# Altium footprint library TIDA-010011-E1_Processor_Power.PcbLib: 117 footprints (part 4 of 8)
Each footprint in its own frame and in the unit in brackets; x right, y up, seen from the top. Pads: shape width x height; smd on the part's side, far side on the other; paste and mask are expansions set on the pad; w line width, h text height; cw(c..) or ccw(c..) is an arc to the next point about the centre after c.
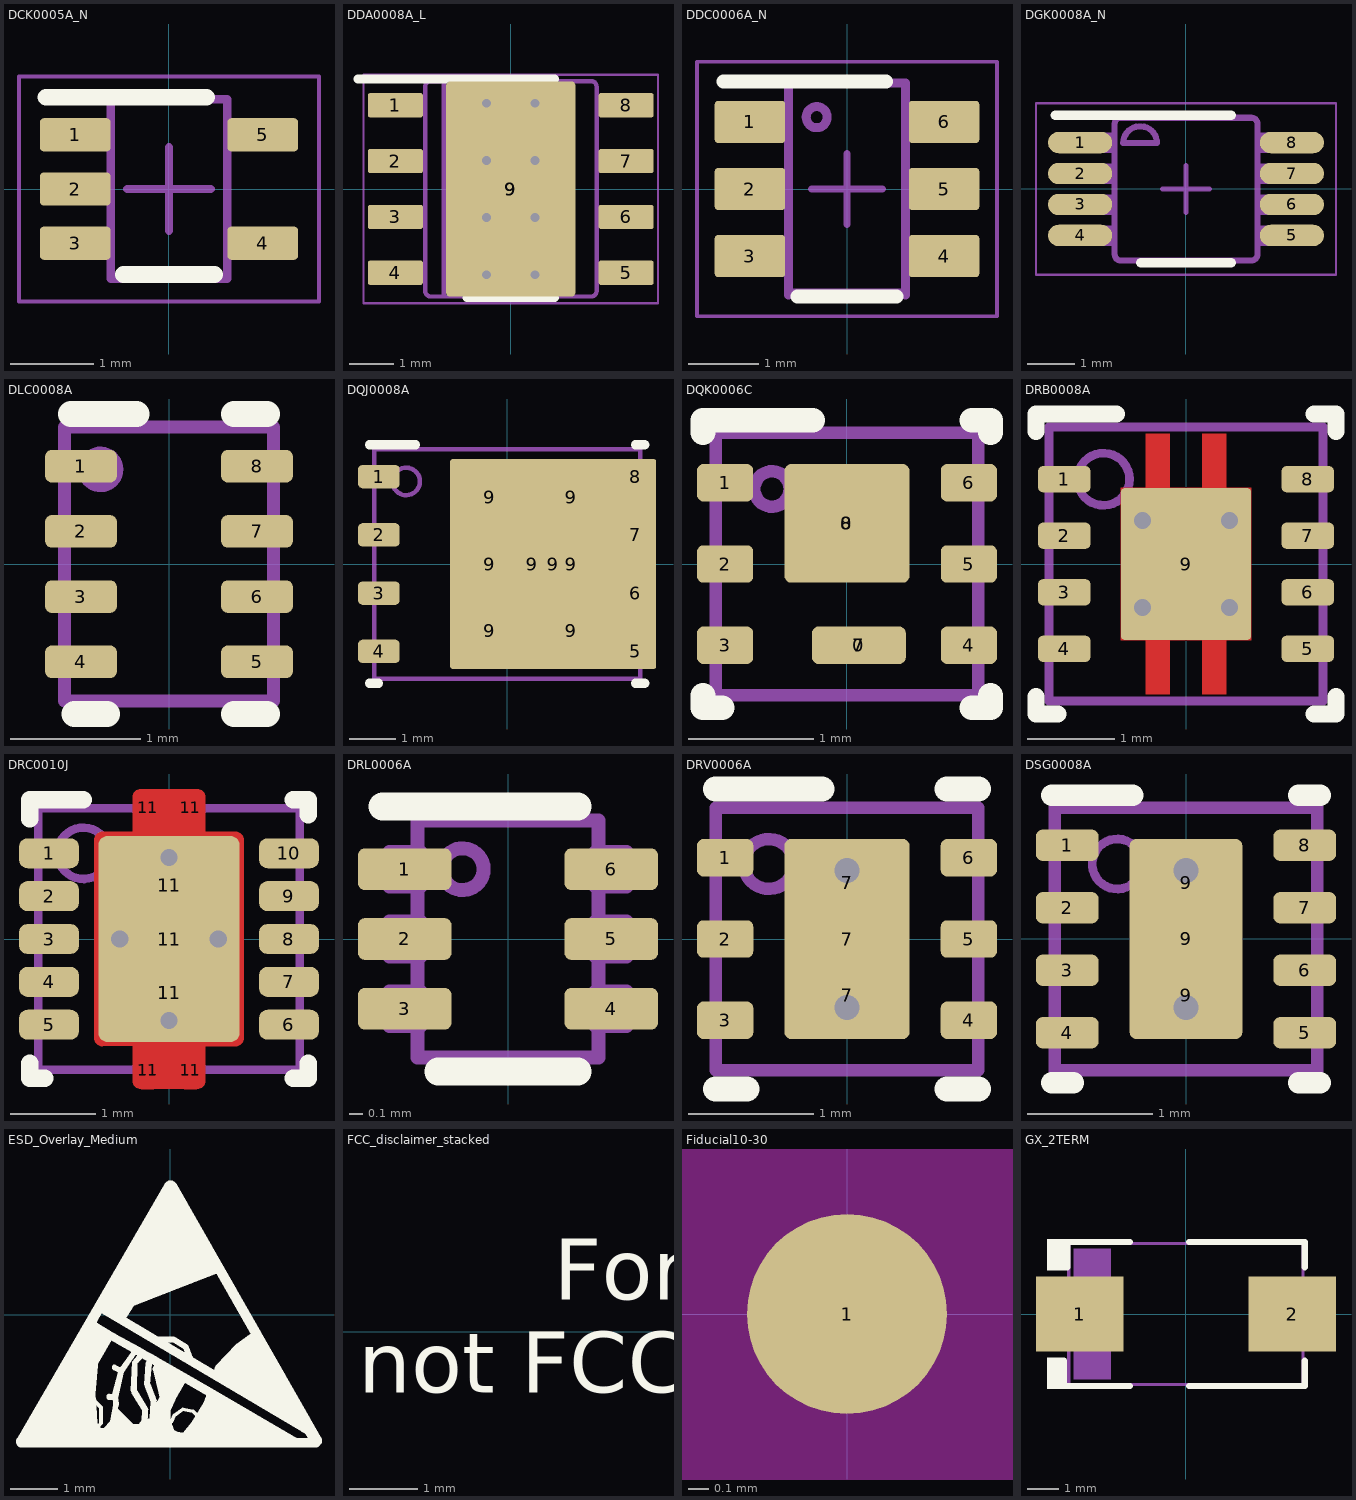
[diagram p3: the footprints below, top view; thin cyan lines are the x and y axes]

## DCK0005A_N [mm] "SOT353, 5-Leads, Body 2x1.3mm, Pitch 0.65mm, Lead Span 2.1mm, IPC Medium Density"
height 1.1
pads (5):
  rrect25% 0.85x0.4 smd: 1(-1.125,0.65) 2(-1.125,0) 3(-1.125,-0.65) 4(1.125,-0.65) 5(1.125,0.65)
Top Overlay:
  lines w0.2: -1.475,1.1 0.45,1.1 ; -0.55,-1.025 0.55,-1.025
Mechanical 5:
  lines w0.1: -0.7,-1.075 0.7,-1.075 0.7,1.075 -0.7,1.075 -0.7,-1.075
  lines w0.127: -0.865,0.762 -0.853,0.762 ; -0.711,-0.763 -0.853,-0.763 -0.865,-0.763 -0.959,-0.763 -1.143,-0.763 -1.143,-0.538 -0.959,-0.538 -0.865,-0.538 -0.853,-0.538 -0.711,-0.538 ; -0.711,-0.113 -0.853,-0.113 -0.865,-0.113 -0.959,-0.113 -1.143,-0.113 -1.143,0.112 -0.959,0.112 -0.865,0.112 -0.853,0.112 -0.711,0.112 ; -0.711,0.537 -0.853,0.537 -0.865,0.537 -0.959,0.537 -1.143,0.537 -1.143,0.762 -0.959,0.762 -0.711,0.762 ; 0.711,-0.763 0.847,-0.763 0.859,-0.763 0.953,-0.763 1.137,-0.763 1.137,-0.538 0.953,-0.538 0.859,-0.538 0.847,-0.538 0.711,-0.538 ; 0.711,0.537 0.847,0.537 0.859,0.537 0.953,0.537 1.137,0.537 1.137,0.762 0.953,0.762 0.859,0.762 0.847,0.762 0.711,0.762
  text ".Designator" at 0.178,-0.718 h0.51
Mechanical 15:
  lines w0.05: -1.8,-1.35 1.8,-1.35 1.8,1.35 -1.8,1.35 -1.8,-1.35
  lines w0.1: -0.5,0 0.5,0 ; 0,-0.5 0,0.5
3D body "DCK0005A.stp": height 0.95, standoff 0, extent -1.14,-1 1.14,1

## DDA0008A_L [mm] "SOIC, 8-Leads, Body 4.95x3.95mm, Pitch 1.27mm, Thermal Pad 2.29.2x2.29mm, IPC High Density"
height 1.68
pads (11):
  rrect18% 1.25x0.55 smd: 1(-2.625,1.905) 2(-2.625,0.635) 3(-2.625,-0.635) 4(-2.625,-1.905) 5(2.625,-1.905) 6(2.625,-0.635) 7(2.625,0.635) 8(2.625,1.905)
  rrect7% 2.95x4.9 smd paste-1.5 mask-1.5: 9(0,0)
  rrect50% 2.34x2.34 on Top Paste: 9(0,0)
  rrect50% 2.34x2.34 on Top Solder: 9(0,0)
via -0.55,0.65 diameter 0.5 hole 0.2
via 0.55,0.65 diameter 0.5 hole 0.2
via -0.55,-0.65 diameter 0.5 hole 0.2
via 0.55,-0.65 diameter 0.5 hole 0.2
via 0.55,1.95 diameter 0.5 hole 0.2
via -0.55,1.95 diameter 0.5 hole 0.2
via -0.55,-1.95 diameter 0.5 hole 0.2
via 0.55,-1.95 diameter 0.5 hole 0.2
Top Overlay:
  lines w0.2: -3.475,2.5 1,2.5 ; -1,-2.475 1,-2.475
Mechanical 5:
  lines w0.1: -1.946,-2.321 ccw(c-1.819,-2.32) -1.82,-2.447 ; -1.946,-2.321 -1.946,-2.32 -1.946,2.329 ; -1.946,2.33 -1.946,2.329 ; -1.524,-2.447 -1.524,2.456 ; -1.946,2.33 cw(c-1.819,2.329) -1.82,2.456 ; -1.819,-2.447 1.826,-2.447 1.827,-2.447 ccw(c1.826,-2.32) 1.953,-2.321 1.953,-2.32 1.953,2.329 ; -1.82,-2.447 -1.819,-2.447 ; -1.82,2.456 -1.819,2.456 ; -1.819,2.456 1.826,2.456 1.827,2.456 cw(c1.826,2.329) 1.953,2.33 ; 1.953,2.329 1.953,2.33 ; -2.975,-2.091 -2.975,-1.71 -2.614,-1.71 -2.497,-1.71 -2.473,-1.71 -2.144,-1.71 -1.946,-1.71 -1.946,-2.091 -2.144,-2.091 -2.473,-2.091 -2.497,-2.091 -2.614,-2.091 -2.975,-2.091 ; -2.975,-0.821 -2.975,-0.44 -2.614,-0.44 -2.497,-0.44 -2.473,-0.44 -2.144,-0.44 -1.946,-0.44 -1.946,-0.821 -2.144,-0.821 -2.473,-0.821 -2.497,-0.821 -2.614,-0.821 -2.975,-0.821 ; -2.975,0.449 -2.975,0.83 -2.614,0.83 -2.497,0.83 -2.473,0.83 -2.144,0.83 -1.946,0.83 -1.946,0.449 -2.144,0.449 -2.473,0.449 -2.497,0.449 -2.614,0.449 -2.975,0.449 ; -2.975,1.719 -2.975,2.1 -2.614,2.1 -2.497,2.1 -2.473,2.1 -2.144,2.1 -1.946,2.1 -1.946,1.719 -2.144,1.719 -2.473,1.719 -2.497,1.719 -2.614,1.719 -2.975,1.719 ; -0.632,1.16 ccw(c-0.632,1.478) -0.632,1.795 ccw(c-0.632,1.478) -0.632,1.16 ; 1.953,-2.091 1.953,-1.71 2.15,-1.71 2.479,-1.71 2.503,-1.71 2.621,-1.71 2.981,-1.71 2.981,-2.091 2.621,-2.091 2.503,-2.091 2.479,-2.091 2.15,-2.091 1.953,-2.091 ; 1.953,-0.821 1.953,-0.44 2.15,-0.44 2.479,-0.44 2.503,-0.44 2.621,-0.44 2.981,-0.44 2.981,-0.821 2.621,-0.821 2.503,-0.821 2.479,-0.821 2.15,-0.821 1.953,-0.821 ; 1.953,0.449 1.953,0.83 2.15,0.83 2.479,0.83 2.503,0.83 2.621,0.83 2.981,0.83 2.981,0.449 2.621,0.449 2.503,0.449 2.479,0.449 2.15,0.449 1.953,0.449 ; 1.953,1.719 1.953,2.1 2.15,2.1 2.479,2.1 2.503,2.1 2.621,2.1 2.981,2.1 2.981,1.719 2.621,1.719 2.503,1.719 2.479,1.719 2.15,1.719 1.953,1.719
  text ".Designator" at 0.245,0.457 h0.51
Mechanical 15:
  lines w0.05: -3.35,-2.6 -3.35,2.6 3.35,2.6 3.35,-2.6 -3.35,-2.6
  lines w0.1: -0.5,0 0.5,0 ; 0,-0.5 0,0.5
3D body "DDA0008A.stp": height 1.55, standoff 0, extent -2.978,-2.451 2.978,2.451

## DDC0006A_N [mm]
height 1.1
pads (6):
  rrect17% 1x0.6 smd: 1(-1.375,0.95) 2(-1.375,0) 3(-1.375,-0.95) 4(1.375,-0.95) 5(1.375,0) 6(1.375,0.95)
Top Overlay:
  lines w0.2: -1.75,1.525 0.55,1.525 ; -0.7,-1.524 0.7,-1.524
Mechanical 5:
  lines w0.127: -0.828,-1.5 -0.828,1.5 0.828,1.5 0.828,-1.5 ; -0.825,-1.165 -1.437,-1.165 -1.437,-0.735 -0.825,-0.735 ; -0.825,-0.215 -1.437,-0.215 -1.437,0.215 -0.825,0.215 ; -0.825,0.735 -1.437,0.735 -1.437,1.165 -0.825,1.165 ; -0.754,-1.47 -0.75,-1.47 0.743,-1.47 0.747,-1.47 ; -0.754,1.5 -0.75,1.5 ; 0.743,1.5 0.747,1.5 ; 0.825,-1.165 1.437,-1.165 1.437,-0.735 0.825,-0.735 ; 0.825,-0.215 1.437,-0.215 1.437,0.215 0.825,0.215 ; 0.825,0.735 1.437,0.735 1.437,1.165 0.825,1.165 ; -0.578,1.018 ccw(c-0.43,1.018) -0.281,1.018 ccw(c-0.43,1.018) -0.578,1.018
  text ".Designator" at -0.246,2.641 h0.51
Mechanical 15:
  lines w0.05: -2.125,-1.8 -2.125,1.8 2.125,1.8 2.125,-1.8 -2.125,-1.8
  lines w0.1: -0.5,0 0.5,0 ; 0,-0.5 0,0.5
3D body "DDC0006A.stp": height 0.92, standoff 0, extent -1.434,-1.485 1.434,1.485

## DGK0008A_N [mm] "TSOP, 8-Leads, Body 3x3mm, Pitch 0.65mm, IPC Medium Density"
height 1.1
pads (8):
  oval 1.35x0.45 smd: 1(-2.225,0.975) 2(-2.225,0.325) 3(-2.225,-0.325) 4(-2.225,-0.975) 5(2.225,-0.975) 6(2.225,-0.325) 7(2.225,0.325) 8(2.225,0.975)
Top Overlay:
  lines w0.2: -2.75,1.55 0.95,1.55 ; -0.95,-1.55 0.95,-1.55
Mechanical 5:
  lines w0.127: -2.45,-1.131 -2.45,-0.826 -2.21,-0.826 -2.091,-0.826 -2.087,-0.826 -1.784,-0.826 -1.498,-0.826 -1.498,-1.131 -1.784,-1.131 -2.087,-1.131 -2.091,-1.131 -2.21,-1.131 -2.45,-1.131 ; -2.45,-0.48 -2.45,-0.175 -2.21,-0.175 -2.091,-0.175 -2.087,-0.175 -1.784,-0.175 -1.498,-0.175 -1.498,-0.48 -1.784,-0.48 -2.087,-0.48 -2.091,-0.48 -2.21,-0.48 -2.45,-0.48 ; -2.45,0.17 -2.45,0.475 -2.21,0.475 -2.091,0.475 -2.087,0.475 -1.784,0.475 -1.498,0.475 -1.498,0.17 -1.784,0.17 -2.087,0.17 -2.091,0.17 -2.21,0.17 -2.45,0.17 ; -2.45,0.82 -2.45,1.125 -2.21,1.125 -2.091,1.125 -2.087,1.125 -1.784,1.125 -1.498,1.125 -1.498,0.82 -1.784,0.82 -2.087,0.82 -2.091,0.82 -2.21,0.82 -2.45,0.82 ; -1.497,-1.377 ccw(c-1.37,-1.374) -1.373,-1.501 -1.371,-1.501 1.373,-1.501 1.375,-1.501 ccw(c1.373,-1.374) 1.5,-1.377 1.5,-1.374 1.5,1.369 1.5,1.372 ccw(c1.373,1.369) 1.375,1.496 1.373,1.496 -1.371,1.496 -1.373,1.496 ccw(c-1.37,1.369) -1.497,1.372 -1.498,1.369 -1.498,-1.374 -1.497,-1.377 ; -1.32,0.962 cw(c-0.964,0.962) -0.609,0.962 -1.32,0.962 ; 1.5,-1.131 1.786,-1.131 2.089,-1.131 2.093,-1.131 2.213,-1.131 2.452,-1.131 2.452,-0.826 2.213,-0.826 2.093,-0.826 2.089,-0.826 1.786,-0.826 1.5,-0.826 1.5,-1.131 ; 1.5,-0.48 1.786,-0.48 2.089,-0.48 2.093,-0.48 2.213,-0.48 2.452,-0.48 2.452,-0.175 2.213,-0.175 2.093,-0.175 2.089,-0.175 1.786,-0.175 1.5,-0.175 1.5,-0.48 ; 1.5,0.17 1.786,0.17 2.089,0.17 2.093,0.17 2.213,0.17 2.452,0.17 2.452,0.475 2.213,0.475 2.093,0.475 2.089,0.475 1.786,0.475 1.5,0.475 1.5,0.17 ; 1.5,0.82 1.786,0.82 2.089,0.82 2.093,0.82 2.213,0.82 2.452,0.82 2.452,1.125 2.213,1.125 2.093,1.125 2.089,1.125 1.786,1.125 1.5,1.125 1.5,0.82
  text ".Designator" at -1.15,-0.3 h0.51
Mechanical 15:
  lines w0.05: -3.15,-1.8 -3.15,1.8 3.15,1.8 3.15,-1.8 -3.15,-1.8
  lines w0.1: -0.5,0 0.5,0 ; 0,-0.5 0,0.5
3D body "DGK0008A.stp": height 0.96, standoff 0, extent -2.451,-1.499 2.451,1.499

## DLC0008A [mm] "VSON-HR-8"
height 1
pads (8):
  rrect40% 0.55x0.25 smd: 1(-0.675,0.75) 2(-0.675,0.25) 3(-0.675,-0.25) 4(-0.675,-0.75) 5(0.675,-0.75) 6(0.675,-0.25) 7(0.675,0.25) 8(0.675,0.75)
Top Overlay:
  lines w0.2: -0.75,1.15 -0.25,1.15 ; -0.725,-1.15 -0.475,-1.15 ; 0.5,-1.15 0.75,-1.15 ; 0.5,1.15 0.75,1.15
Mechanical 5:
  circle w0.1: c-0.525,0.725 r0.125
  lines w0.1: -0.8,-1.05 0.8,-1.05 0.8,1.05 -0.8,1.05 -0.8,-1.05
  text ".Designator" at 0.432,-2.616 h0.51
3D body: height 1, standoff 0, extent -0.799,-1.049 0.799,1.049
3D body: height 1.02, standoff 0.5, extent -0.549,0.601 -0.301,0.849

## DQJ0008A [mm] "SMD, 8-Leads, Body 5.75x4.9mm"
height 1.1
pads (16):
  rrect39% 0.91x0.51 smd paste-0.05 mask-0.05: 1(-2.795,1.905) 2(-2.795,0.635) 3(-2.795,-0.635) 4(-2.795,-1.905) 5(2.795,-1.905) 6(2.795,-0.635) 7(2.795,0.635) 8(2.795,1.905)
  rrect50% 1.58x1.25 on Top Paste: 9(-0.38,-1.45) 9(-0.38,0) 9(-0.38,1.45) 9(1.4,-1.45) 9(1.4,0) 9(1.4,1.45)
  rrect50% 3.48x4.47 on Top Solder: 9(0.55,0)
  rrect2% 4.49x4.57 smd paste-2.5 mask-2.5: 9(1.005,0)
Top Overlay:
  lines w0.2: -3,-2.6 -2.8,-2.6 ; -3,2.6 -2,2.6 ; 2.8,-2.6 3,-2.6 ; 2.8,2.6 3,2.6
Top Solder:
  rectangle: 2.25,-0.84 2.475,-0.43
  rectangle: 2.25,-2.11 2.475,-1.7
  rectangle: 2.25,1.7 2.475,2.11
  rectangle: 2.25,0.43 2.475,0.84
Mechanical 5:
  circle w0.1: c-2.2,1.8 r0.3
  lines w0.1: -2.9,-2.5 -2.9,2.5 2.9,2.5 2.9,-2.5 -2.9,-2.5
  text ".Designator" at 0.026,-0.404 h0.51
3D body "DQJ0008A.stp": height 1.15, standoff 0, extent -3.13,-2.45 3.13,2.45

## DQK0006C [mm] "WSON"
height 0.8
pads (10):
  rrect50% 0.9x0.86 on Top Paste: 0(0,0.325)
  rrect50% 0.7x0.29 on Top Paste: 0(0.095,-0.65)
  rrect33% 0.45x0.3 smd: 1(-0.975,0.65) 2(-0.975,0) 3(-0.975,-0.65) 4(0.975,-0.65) 5(0.975,0) 6(0.975,0.65)
  rrect33% 0.75x0.3 smd paste-0.15: 7(0.095,-0.65)
  rrect11% 1x0.95 smd paste-0.5: 8(0,0.325)
Top Overlay:
  lines w0.2: -1.15,-1.05 -1.15,-1.15 -1,-1.15 ; -1.15,1.05 -1.15,1.15 -0.275,1.15 ; 1,-1.15 1.15,-1.15 1.15,-1.05 ; 1,1.15 1.15,1.15 1.15,1.05
Mechanical 5:
  circle w0.1: c-0.6,0.6 r0.141
  lines w0.1: -1.05,-1.05 1.05,-1.05 1.05,1.05 -1.05,1.05 -1.05,-1.05
  text ".Designator" at -0.533,-0.388 h0.51
3D body "DQK0006C.stp": height 0.82, standoff 0, extent -1,-1 1,1

## DRB0008A [mm] "SON, 8-Leads, Body 3x3mm, Pitch 0.65mm, Thermal Pad 1.75x1.5mm, TI Recommended"
height 1
pads (9):
  rrect33% 0.6x0.3 smd: 1(-1.4,0.975) 2(-1.4,0.325) 3(-1.4,-0.325) 4(-1.4,-0.975) 5(1.4,-0.975) 6(1.4,-0.325) 7(1.4,0.325) 8(1.4,0.975)
  rrect7% 1.5x1.75 smd paste-0.75: 9(0,0)
via 0.5,0.5 diameter 0.5 hole 0.2
via -0.5,0.5 diameter 0.5 hole 0.2
via -0.5,-0.5 diameter 0.5 hole 0.2
via 0.5,-0.5 diameter 0.5 hole 0.2
Top Layer:
  region: -0.465,-1.5 -0.465,-0.875 -0.75,-0.875 -0.75,0.875 -0.465,0.875 -0.465,1.5 -0.185,1.5 -0.185,0.875 0.185,0.875 0.185,1.5 0.465,1.5 0.465,0.875 0.75,0.875 0.75,-0.875 0.465,-0.875 0.465,-1.5 0.185,-1.5 0.185,-0.875 -0.185,-0.875 -0.185,-1.5
Top Overlay:
  lines w0.2: -1.725,-1.525 -1.725,-1.725 -1.475,-1.725 ; -1.725,1.525 -1.725,1.725 -0.8,1.725 ; 1.475,-1.725 1.725,-1.725 1.725,-1.525 ; 1.475,1.725 1.725,1.725 1.725,1.525
Top Paste:
  rectangle: -0.691,-0.792 0.692,0.793
Mechanical 5:
  circle w0.1: c-0.95,0.975 r0.3
  lines w0.1: -1.575,-1.575 -1.575,1.575 1.575,1.575 1.575,-1.575 -1.575,-1.575
  text ".Designator" at -0.226,0.624 h0.51
3D body: height 1, standoff 0, extent -1.575,-1.575 1.575,1.575
3D body: height 1.01, standoff 0.8, extent -1.249,0.676 -0.651,1.274

## DRC0010J [mm] "SON, 10-Leads, Body 3x3mm, Pitch 0.5mm, Thermal Pad 2.4x1.65mm, TI Recommended"
height 1
pads (17):
  rrect57% 0.7x0.35 smd paste-0.05 mask-0.05: 1(-1.4,1) 2(-1.4,0.5) 3(-1.4,0) 4(-1.4,-0.5) 5(-1.4,-1) 6(1.4,-1) 7(1.4,-0.5) 8(1.4,0) 9(1.4,0.5) 10(1.4,1)
  rrect50% 0.25x0.34 on Top Paste: 11(-0.25,-1.53) 11(-0.25,1.53) 11(0.25,-1.53) 11(0.25,1.53)
  rrect50% 1.5x1.06 on Top Paste: 11(0,-0.63) 11(0,0.63)
  rrect12% 1.65x2.4 smd paste-1 mask-2: 11(0,0)
via 0,-0.95 diameter 0.5 hole 0.2
via 0,0.95 diameter 0.5 hole 0.2
via -0.575,0 diameter 0.5 hole 0.2
via 0.575,0 diameter 0.5 hole 0.2
Top Layer:
  rectangle: -0.25,1.1 0.25,1.75
  rectangle: -0.25,-1.75 0.25,-1.1
  region: -0.775,-1.25 -0.425,-1.25 -0.425,-1.65 -0.425,-1.67 -0.41,-1.707 -0.382,-1.735 -0.345,-1.75 -0.325,-1.75 -0.175,-1.75 -0.155,-1.75 -0.118,-1.735 -0.09,-1.707 -0.075,-1.67 -0.075,-1.65 -0.075,-1.25 0.075,-1.25 0.075,-1.65 0.075,-1.67 0.09,-1.707 0.118,-1.735 0.155,-1.75 0.175,-1.75 0.325,-1.75 0.345,-1.75 0.382,-1.735 0.41,-1.707 0.425,-1.67 0.425,-1.65 0.425,-1.25 0.775,-1.25 0.795,-1.25 0.832,-1.235 0.86,-1.207 0.875,-1.17 0.875,-1.15 0.875,1.15 0.875,1.17 0.86,1.207 0.832,1.235 0.795,1.25 0.775,1.25 0.425,1.25 0.425,1.65 0.425,1.67 0.41,1.707 0.382,1.735 0.345,1.75 0.325,1.75 0.175,1.75 0.155,1.75 0.118,1.735 0.09,1.707 0.075,1.67 0.075,1.65 0.075,1.25 -0.075,1.25 -0.075,1.65 -0.075,1.67 -0.09,1.707 -0.118,1.735 -0.155,1.75 -0.175,1.75 -0.325,1.75 -0.345,1.75 -0.382,1.735 -0.41,1.707 -0.425,1.67 -0.425,1.65 -0.425,1.25 -0.775,1.25 -0.795,1.25 -0.832,1.235 -0.86,1.207 -0.875,1.17 -0.875,1.15 -0.875,-1.15 -0.875,-1.17 -0.86,-1.207 -0.832,-1.235 -0.795,-1.25
Top Overlay:
  lines w0.2: -1.625,-1.45 -1.625,-1.625 -1.45,-1.625 ; -1.625,1.4 -1.625,1.625 -1,1.625 ; 1.45,-1.625 1.625,-1.625 1.625,-1.45 ; 1.45,1.625 1.625,1.625 1.625,1.45
Mechanical 5:
  circle w0.1: c-1,1 r0.3
  lines w0.1: -1.525,-1.525 1.525,-1.525 1.525,1.525 -1.525,1.525 -1.525,-1.525
  text ".Designator" at 0.369,0.74 h0.51
3D body "DRC0010J.stp": height 0.77, standoff 0, extent -1.5,-1.5 1.5,1.5

## DRL0006A [mm] "SOTFL, 6-Flat Leads, Body 1.2x1.6x0.6mm, Pitch 0.5mm, TI recommended"
height 0.6
pads (6):
  rrect33% 0.67x0.3 smd: 1(-0.74,0.5) 2(-0.74,0) 3(-0.74,-0.5) 4(0.74,-0.5) 5(0.74,0) 6(0.74,0.5)
Top Overlay:
  lines w0.2: -0.9,0.95 0.5,0.95 ; -0.5,-0.95 0.5,-0.95
Mechanical 5:
  circle w0.1: c-0.325,0.5 r0.15
  lines w0.1: -0.65,-0.625 -0.65,-0.85 0.65,-0.85 0.65,-0.625 ; -0.65,-0.375 -0.65,-0.125 ; -0.65,0.125 -0.65,0.375 ; -0.65,0.625 -0.65,0.85 0.65,0.85 0.65,0.625 ; 0.65,-0.375 0.65,0.375 ; -0.85,-0.625 -0.85,-0.375 -0.627,-0.375 -0.627,-0.625 -0.85,-0.625 ; -0.85,-0.125 -0.627,-0.125 -0.627,0.125 -0.85,0.125 -0.85,-0.125 ; -0.85,0.375 -0.85,0.625 -0.627,0.625 -0.627,0.375 -0.85,0.375 ; 0.627,-0.625 0.627,-0.375 0.85,-0.375 0.85,-0.625 0.627,-0.625 ; 0.627,-0.125 0.85,-0.125 0.85,0.125 0.627,0.125 0.627,-0.125 ; 0.627,0.375 0.627,0.625 0.85,0.625 0.85,0.375 0.627,0.375
  text ".Designator" at -0.102,2.642 h0.51
3D body "DRL0006A.stp": height 0.61, standoff 0.01, extent -0.8,-0.8 0.8,0.8

## DRV0006A [mm] "SON, 6-Leads, Body 2x2mm, Pitch 0.65mm, Thermal Pad 1.6x1mm, TI Recommended"
height 0.8
pads (9):
  rrect33% 0.45x0.3 smd: 1(-0.975,0.65) 2(-0.975,0) 3(-0.975,-0.65) 4(0.975,-0.65) 5(0.975,0) 6(0.975,0.65)
  rrect50% 1x0.7 on Top Paste: 7(0,-0.45) 7(0,0.45)
  rrect10% 1x1.6 smd paste-0.5: 7(0,0)
via 0,0.55 diameter 0.5 hole 0.2
via 0,-0.55 diameter 0.5 hole 0.2
Top Overlay:
  lines w0.2: -1.05,-1.2 -0.8,-1.2 ; -1.05,1.2 -0.2,1.2 ; 0.8,-1.2 1.05,-1.2 ; 0.8,1.2 1.05,1.2
Mechanical 5:
  circle w0.1: c-0.625,0.6 r0.2
  lines w0.1: -1.05,-1.05 -1.05,1.05 1.05,1.05 1.05,-1.05 -1.05,-1.05
  text ".Designator" at -0.012,0.552 h0.51
3D body: height 0.8, standoff 0, extent -1.05,-1.05 1.05,1.05
3D body: height 0.81, standoff 0.5, extent -0.824,0.401 -0.426,0.799

## DSG0008A [mm] "SON, 8-Leads, Body 2x2mm, Pitch 0.5mm, Thermal Pad 1.6x0.9mm, TI Recommended"
height 0.8
pads (11):
  rrect40% 0.5x0.25 smd: 1(-0.95,0.75) 2(-0.95,0.25) 3(-0.95,-0.25) 4(-0.95,-0.75) 5(0.95,-0.75) 6(0.95,-0.25) 7(0.95,0.25) 8(0.95,0.75)
  rrect50% 0.9x0.7 on Top Paste: 9(0,-0.45) 9(0,0.45)
  rrect11% 0.9x1.6 smd paste-0.45: 9(0,0)
via 0,-0.55 diameter 0.5 hole 0.2
via 0,0.55 diameter 0.5 hole 0.2
Top Overlay:
  lines w0.17: -1.075,-1.15 -0.9,-1.15 ; -1.075,1.15 -0.425,1.15 ; 0.9,-1.15 1.075,-1.15 ; 0.9,1.15 1.075,1.15
Mechanical 5:
  circle w0.07: c-0.55,0.6 r0.2
  lines w0.1: -1.05,-1.05 1.05,-1.05 1.05,1.05 -1.05,1.05 -1.05,-1.05
  text ".Designator" at -0.007,0.668 h0.51
3D body "DSG0008A.stp": height 0.77, standoff 0, extent -1,-1 1,1

## ESD_Overlay_Medium [mm]
height 33
Top Overlay:
  drawing of 6916 lines, arcs and shapes, not listed

## FCC_disclaimer_stacked [mm]
height 33
Top Overlay:
  text "For evaluation only;" at -5.834,0.178 h1.52
  text "not FCC approved for resale." at -8.688,-1.178 h1.52

## Fiducial10-30 [mm]
height 3
pads (1):
  round 1 smd mask+1: 1(0,0)
Top Layer keep-out:
  circle w1.678: c0,0 r0.75

## GX_2TERM [mm] "PANASONIC"
height 2
pads (2):
  rect 2.8x2.4 smd: 1(-3.4,0) 2(3.4,0)
Top Overlay:
  rectangle: -4.45,-2.4 -3.9,-1.4
  rectangle: -4.45,1.4 -3.8,2.4
  lines w0.2: -3.9,-1.5 -3.9,-2.3 -1.8,-2.3 ; -3.8,1.5 -3.8,2.3 -1.8,2.3 ; 0.1,-2.3 3.8,-2.3 3.8,-1.5 ; 0.1,2.3 3.8,2.3 3.8,1.5
Mechanical 5:
  rectangle: -3.6,-2.1 -2.4,2.1
  lines w0.1: -3.75,-2.25 3.75,-2.25 3.75,2.25 -3.75,2.25 -3.75,-2.25
  text ".Designator" at 1.473,0.356 h0.51
3D body: height 2, standoff 0, extent -3.749,-2.249 3.749,2.249
3D body: height 2.01, standoff 1, extent -3.599,-2.099 -2.401,2.099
